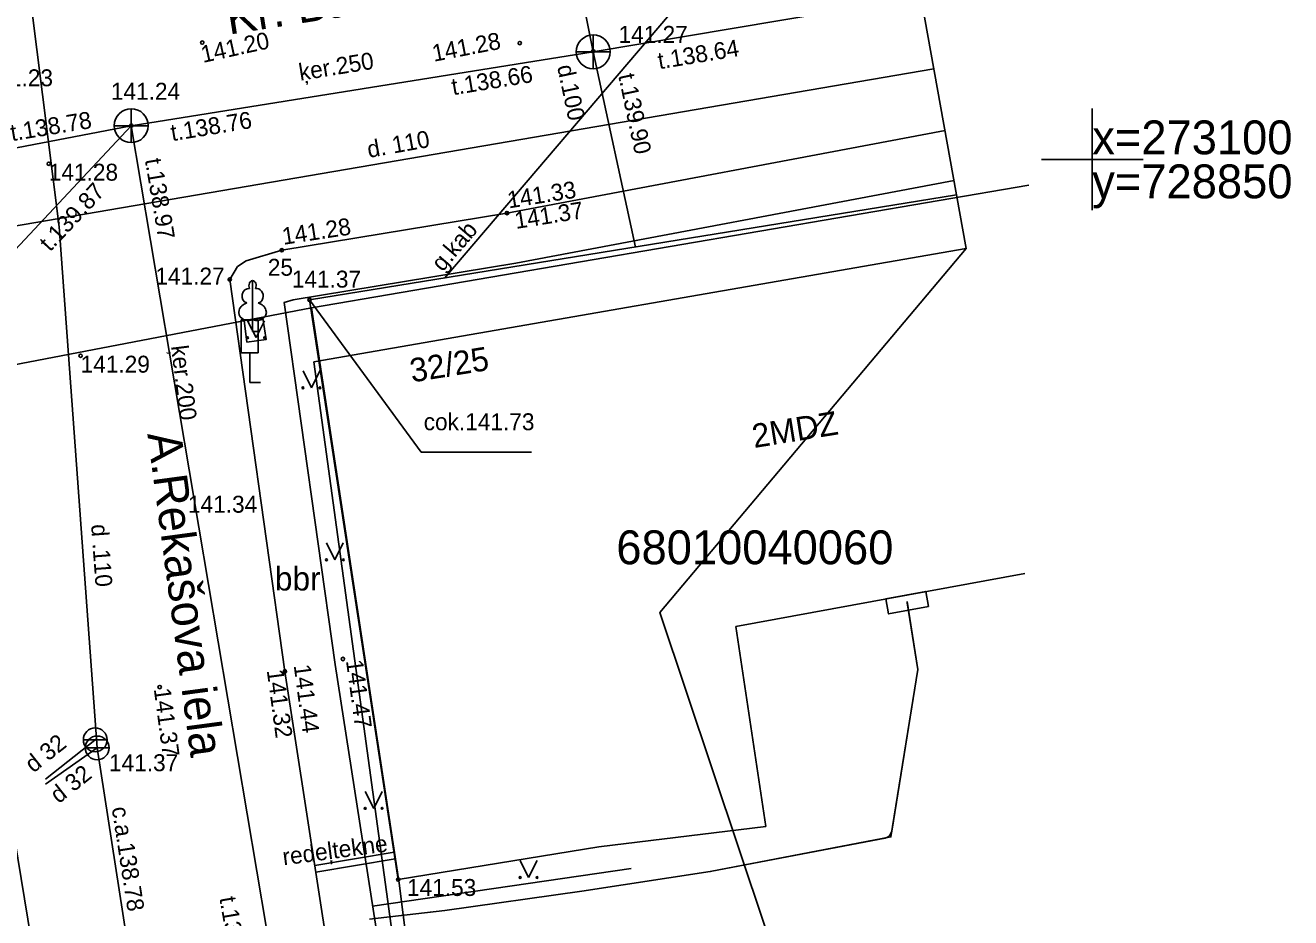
# Model space of a CAD drawing. Extents: x 728710 to 728960, y 272811 to 273475.
# Drawn here: x 728818.5 to 728855.86, y 273077.6 to 273103.96 of the extents above; entities that cross this region are included whole.
import ezdxf

# ---------------------------------------------------------------- set-up
doc = ezdxf.new("R2010")
doc.units = 0
for name, color, linetype in [('GEOD_KORD_####_TKST_#', 7, 'Continuous'), ('Level 10', 7, 'Continuous'), ('Level 15', 7, 'Continuous'), ('Level 17', 7, 'Continuous'), ('Level 23', 7, 'Continuous'), ('Level 29', 7, 'Continuous'), ('Level 3', 7, 'Continuous'), ('Level 36', 7, 'Continuous'), ('Level 39', 7, 'Continuous'), ('Level 4', 7, 'Continuous'), ('Level 48', 7, 'Continuous'), ('Level 49', 7, 'Continuous'), ('Level 50', 7, 'Continuous'), ('Level 54', 7, 'Continuous'), ('Level 55', 7, 'Continuous'), ('Level 57', 7, 'Continuous'), ('Level 58', 7, 'Continuous'), ('Level 59', 7, 'Continuous'), ('Level 60', 7, 'Continuous'), ('Level 62', 7, 'Continuous'), ('Level 9', 7, 'Continuous'), ('PNTNO', 7, 'Continuous'), ('RAMI_UZMR_####_####_#', 7, 'Continuous'), ('RELJ_NOGA_####_####_#', 7, 'Continuous'), ('ROBZ_ELEM_####_####_#', 7, 'Continuous'), ('ROBZ_KADS_####_TKST_#', 7, 'Continuous'), ('ROBZ_UZMR_####_####_#', 7, 'Continuous'), ('SAKT_VADV_PKAB_TKST_#', 7, 'Continuous'), ('TERT_ELEM_####_####_#', 7, 'Continuous'), ('TERT_KONT_####_####_#', 7, 'Continuous')]:
    doc.layers.add(name, color=color, linetype=linetype)

msp = doc.modelspace()

# ---------------------------------------------------------------- linework, layer by layer
at = {"layer": 'Level 10'}
for p, q in [((728850, 273101.5), (728850, 273100)), ((728848.5, 273100), (728850, 273100)), ((728850, 273100), (728850, 273098.5)), ((728850, 273100), (728851.5, 273100))]:
    msp.add_line(p, q, dxfattribs=at)
at = {"layer": 'Level 15'}
msp.add_lwpolyline([(728843.903, 273087.018), (728845.083, 273087.236), (728845.165, 273086.793), (728843.985, 273086.575)], close=True, dxfattribs=at)
at = {"layer": 'Level 17'}
for p, q in [((728845.326, 273102.67), (728810.333, 273096.686)), ((728819.089, 273081.692), (728820.6, 273082.885)), ((728819.097, 273081.543), (728820.62, 273082.615))]:
    msp.add_line(p, q, dxfattribs=at)
for points in [[(728814.387, 273138.519), (728819.492, 273098.009)], [(728819.492, 273098.009), (728820.62, 273082.615)], [(728820.62, 273082.615), (728824.557, 273057.19)]]:
    msp.add_lwpolyline(points, dxfattribs=at)
at = {"layer": 'Level 23'}
for points in [[(728821.624, 273100.995), (728835.266, 273103.178), (728833.756, 273110.699)], [(728835.266, 273103.178), (728844.94, 273104.815)], [(728835.266, 273103.178), (728836.517, 273097.411)], [(728805.243, 273097.85), (728821.624, 273100.995), (728813.478, 273092.29)], [(728821.624, 273100.995), (728826.189, 273073.896), (728840.452, 273076.388)]]:
    msp.add_lwpolyline(points, dxfattribs=at)
at = {"layer": 'Level 29'}
for p, q in [((728835.266, 273102.678), (728835.266, 273103.678)), ((728834.766, 273103.178), (728835.766, 273103.178)), ((728821.624, 273100.495), (728821.624, 273101.495)), ((728821.124, 273100.995), (728822.124, 273100.995))]:
    msp.add_line(p, q, dxfattribs=at)
for centre in [(728835.266, 273103.178), (728821.624, 273100.995)]:
    msp.add_circle(centre, 0.5, dxfattribs=at)
at = {"layer": 'Level 3'}
for p, q in [((728845.995, 273098.953), (728826.892, 273095.851)), ((728826.892, 273095.851), (728829.508, 273078.726)), ((728848.008, 273087.77), (728839.473, 273086.203)), ((728839.473, 273086.203), (728840.359, 273080.29)), ((728840.359, 273080.29), (728835.436, 273079.689)), ((728829.508, 273078.726), (728835.436, 273079.689))]:
    msp.add_line(p, q, dxfattribs=at)
at = {"layer": 'Level 36'}
msp.add_lwpolyline([(728829.43, 273077.644), (728830.885, 273077.81), (728834.933, 273078.385), (728838.722, 273078.96), (728844.053, 273079.984), (728844.848, 273084.934), (728844.534, 273086.905)], dxfattribs=at)
at = {"layer": 'Level 39'}
for p, q in [((728820.211, 273082.855), (728820.913, 273082.855)), ((728820.561, 273082.855), (728820.561, 273082.856)), ((728820.269, 273082.615), (728820.971, 273082.615)), ((728820.619, 273082.615), (728820.619, 273082.616))]:
    msp.add_line(p, q, dxfattribs=at)
for centre in [(728820.562, 273082.855), (728820.62, 273082.615)]:
    msp.add_circle(centre, 0.351, dxfattribs=at)
at = {"layer": 'Level 4'}
for points in [[(728845.654, 273100.85), (728832.719, 273098.413), (728826.071, 273097.316), (728825.017, 273097.001), (728824.765, 273096.832), (728824.532, 273096.455), (728824.532, 273096.455), (728826.161, 273084.877), (728827.437, 273076.575), (728829.749, 273059.3), (728831.728, 273043.761), (728834.021, 273027.538), (728834.782, 273021.709), (728836.279, 273011.943), (728839.357, 272993.501), (728839.499, 272992.383), (728841.21, 272978.381), (728843.301, 272966.86), (728843.797, 272965.94)], [(728845.919, 273099.374), (728832.98, 273096.936), (728826.409, 273095.852), (728826.143, 273095.772), (728827.647, 273085.083), (728828.941, 273076.709), (728831.314, 273059.418), (728833.202, 273044.226), (728835.526, 273027.512), (728836.266, 273021.924), (728837.76, 273012.18), (728840.331, 272994.327), (728840.331, 272994.327), (728840.331, 272994.327), (728842.687, 272979.229), (728844.615, 272968.066)], [(728791.727, 273091.506), (728811.654, 273095.023), (728814.654, 273095.178), (728815.22, 273095.032), (728815.785, 273094.657), (728816.384, 273093.154), (728816.384, 273093.154), (728817.477, 273084.163), (728819.263, 273073.354), (728821.261, 273057.957), (728825.757, 273025.679), (728827.763, 273011.141), (728832.943, 272977.993), (728834.913, 272963.328)], [(728824.957, 273095.241), (728825.042, 273094.601), (728825.605, 273094.676), (728825.508, 273095.31), (728824.957, 273095.241)], [(728828.751, 273077.94), (728836.384, 273079.051)]]:
    msp.add_lwpolyline(points, dxfattribs=at)
at = {"layer": 'Level 48'}
for centre in [(728823.723, 273103.448), (728833.097, 273103.434), (728835.266, 273103.195), (728821.624, 273100.995), (728819.19, 273099.871), (728832.719, 273098.413), (728826.071, 273097.316), (728824.532, 273096.455), (728826.892, 273095.851), (728820.13, 273094.2), (728827.875, 273085.242), (728826.161, 273084.877), (728822.464, 273084.411), (728829.508, 273078.726)]:
    msp.add_circle(centre, 0.05, dxfattribs=at)
at = {"layer": 'Level 49'}
for p, q in [((728825.372, 273095.255), (728824.872, 273095.255)), ((728824.872, 273094.286), (728824.872, 273095.255)), ((728825.372, 273094.286), (728825.372, 273095.255)), ((728825.372, 273094.286), (728824.872, 273094.286)), ((728825.126, 273094.286), (728825.126, 273093.408)), ((728825.126, 273093.408), (728825.441, 273093.408))]:
    msp.add_line(p, q, dxfattribs=at)
at = {"layer": 'Level 9'}
for p, q in [((728829.384, 273079.536), (728827.042, 273079.144)), ((728829.415, 273079.338), (728827.073, 273078.946))]:
    msp.add_line(p, q, dxfattribs=at)
msp.add_lwpolyline([(728826.892, 273095.851), (728830.187, 273091.35), (728833.447, 273091.35)], dxfattribs=at)
at = {"layer": 'RAMI_UZMR_####_####_#'}
for points in [[(728848.126, 273018.981), (728842.745, 273067.512), (728841.027, 273070.984), (728840.357, 273077.286), (728837.229, 273086.616), (728846.28, 273097.37), (728843.445, 273113.117), (728841.542, 273127.507), (728832.527, 273130.942), (728826.701, 273137.145), (728825.388, 273148.763), (728838.211, 273156.68), (728838.026, 273158.297), (728833.202, 273166.507)], [(728830.884, 273096.499), (728844.722, 273112.736)]]:
    msp.add_lwpolyline(points, dxfattribs=at)
at = {"layer": 'ROBZ_ELEM_####_####_#'}
for points in [[(728846.28, 273097.37), (728827.017, 273094.024)], [(728827.017, 273094.024), (728832.315, 273055.38), (728845.254, 272968.134)]]:
    msp.add_lwpolyline(points, dxfattribs=at)
at = {"layer": 'ROBZ_UZMR_####_####_#'}
for p, q in [((728826.945, 273095.617), (728848.13, 273099.241)), ((728812.375, 273092.814), (728826.945, 273095.617)), ((728826.945, 273095.617), (728829.532, 273078.616)), ((728829.532, 273078.616), (728830.131, 273073.976))]:
    msp.add_line(p, q, dxfattribs=at)
at = {"layer": 'TERT_ELEM_####_####_#'}
for points in [[(728844.539, 273086.936), (728844.848, 273084.934), (728844.081, 273080.157)], [(728843.881, 273079.951), (728838.722, 273078.96), (728834.933, 273078.385), (728830.885, 273077.81), (728828.661, 273077.556)]]:
    msp.add_lwpolyline(points, dxfattribs=at)
msp.add_arc((728843.834, 273080.196), 0.25, 280.8732, 350.8759, dxfattribs=at)
at = {"layer": 'TERT_KONT_####_####_#'}
for p, q in [((728825.062, 273095.234), (728825.312, 273094.734)), ((728825.207, 273095.264), (728825.207, 273094.917)), ((728825.312, 273094.734), (728825.562, 273095.234)), ((728825.207, 273094.917), (728825.407, 273094.917)), ((728826.697, 273093.753), (728826.947, 273093.253)), ((728826.947, 273093.253), (728827.197, 273093.753)), ((728827.387, 273088.671), (728827.637, 273088.171)), ((728827.637, 273088.171), (728827.887, 273088.671)), ((728828.533, 273081.33), (728828.783, 273080.83)), ((728828.783, 273080.83), (728829.033, 273081.33)), ((728833.106, 273079.287), (728833.356, 273078.787)), ((728833.356, 273078.787), (728833.606, 273079.287))]:
    msp.add_line(p, q, dxfattribs=at)
for points in [[(728825.207, 273096.417), (728825.207, 273095.264)], [(728825.297, 273096.185), (728825.296, 273096.186)]]:
    msp.add_lwpolyline(points, dxfattribs=at)
for centre, radius in [((728825.062, 273094.733), 0.028), ((728825.562, 273094.733), 0.0263), ((728826.696, 273093.252), 0.028), ((728827.196, 273093.252), 0.0263), ((728827.387, 273088.171), 0.028), ((728827.887, 273088.171), 0.0263), ((728828.532, 273080.83), 0.028), ((728829.032, 273080.83), 0.0263), ((728833.105, 273078.787), 0.028), ((728833.605, 273078.787), 0.0263)]:
    msp.add_circle(centre, radius, dxfattribs=at)
for centre, major_axis, ratio, start_param, end_param in [((728825.079, 273095.972), (-0.039, -0.212), 0.861323, 3.141593, 6.283185), ((728825.207, 273096.267), (0, -0.15), 0.707107, 3.14537, 5.287485), ((728825.207, 273096.267), (0, -0.15), 0.707107, 0.995701, 3.137816), ((728825.335, 273095.972), (0.039, -0.212), 0.861323, 0, 3.141593), ((728825.117, 273095.51), (0.307, 0.095), 0.814445, 1.570796, 4.752015), ((728825.297, 273095.51), (-0.307, 0.095), 0.814445, 1.531171, 4.712389)]:
    msp.add_ellipse(centre, major_axis=major_axis, ratio=ratio, start_param=start_param, end_param=end_param, dxfattribs=at)

# ---------------------------------------------------------------- texts
at = {"layer": 'GEOD_KORD_####_TKST_#'}
for s, p in [('x=273100', (728850, 273100.15)), ('y=728850', (728850, 273098.85))]:
    msp.add_text(s, height=1, dxfattribs=at).set_placement(p)
at = {"layer": 'Level 29'}
for s, p in [('141.27', (728836.013, 273103.442)), ('141.24', (728821.023, 273101.761))]:
    msp.add_text(s, height=0.5, dxfattribs=at).set_placement(p)
at = {"layer": 'Level 50'}
msp.add_text('cok.141.73', height=0.5, dxfattribs=at).set_placement((728830.26, 273091.999))
at = {"layer": 'Level 54'}
for s, rotation, p in [('Kr. Barona iela', 8.9676, (728824.513, 273103.683)), ('A.Rekašova iela', 277.641, (728822.099, 273091.891))]:
    msp.add_text(s, height=1, rotation=rotation, dxfattribs=at).set_placement(p)
at = {"layer": 'Level 55'}
for s, rotation, p in [('d. 110', 10.171, (728828.639, 273100.041)), ('d .110', 274.1909, (728820.438, 273089.209)), ('d 32', 38.5497, (728818.736, 273081.86)), ('d 32', 38.4214, (728819.481, 273080.952)), ('c.a.138.78', 278.8022, (728821.046, 273080.844))]:
    msp.add_text(s, height=0.5, rotation=rotation, dxfattribs=at).set_placement(p)
at = {"layer": 'Level 57'}
for s, rotation, p in [('141.20', 12.3724, (728823.743, 273102.848)), ('141.28', 10.9426, (728830.56, 273102.882)), ('141.33', 9.0652, (728832.771, 273098.55)), ('141.37', 9.0266, (728832.985, 273097.944)), ('141.28', 8.6712, (728826.118, 273097.475)), ('141.44', 277.4911, (728826.421, 273085.054)), ('141.47', 277.7155, (728827.964, 273085.19)), ('141.32', 277.6342, (728825.625, 273084.905)), ('141.37', 277.5622, (728822.29, 273084.354))]:
    msp.add_text(s, height=0.5, rotation=rotation, dxfattribs=at).set_placement(p)
for s, p in [('141.23', (728817.27, 273102.159)), ('141.28', (728819.19, 273099.371)), ('141.27', (728822.337, 273096.302)), ('141.37', (728826.366, 273096.212)), ('141.29', (728820.13, 273093.7)), (' 141.34', (728823.114, 273089.563)), (' 141.53', (728829.581, 273078.242))]:
    msp.add_text(s, height=0.5, dxfattribs=at).set_placement(p)
at = {"layer": 'Level 58'}
msp.add_text('bbr', height=0.7, dxfattribs=at).set_placement((728825.865, 273087.265))
at = {"layer": 'Level 59'}
msp.add_text('2MDZ', height=0.7, rotation=9.224, dxfattribs=at).set_placement((728840.017, 273091.472))
at = {"layer": 'Level 60'}
for s, rotation, p in [('t.138.64', 9.426, (728837.216, 273102.66)), ('ķer.250', 9.272, (728826.615, 273102.321)), ('t.138.66', 9.426, (728831.127, 273101.892)), ('d.100', 281.932, (728834.197, 273102.744)), ('t.139.90', 281.932, (728836.002, 273102.481)), ('t.138.78', 9.383, (728818.101, 273100.536)), ('t.138.76', 9.383, (728822.833, 273100.536)), ('t.138.97', 279.562, (728822.025, 273099.989)), ('t.139.87', 46.899, (728819.226, 273097.251)), ('ķer.200', 277.044, (728822.797, 273094.48)), ('t.139.30', 279.562, (728824.227, 273078.183))]:
    msp.add_text(s, height=0.5, rotation=rotation, dxfattribs=at).set_placement(p)
at = {"layer": 'Level 62'}
msp.add_text('32/25', height=0.7, rotation=9.224, dxfattribs=at).set_placement((728829.913, 273093.408))
at = {"layer": 'Level 9'}
msp.add_text('redeļtekne', height=0.5, rotation=7.5675, dxfattribs=at).set_placement((728826.124, 273079.145))
at = {"layer": 'PNTNO'}
msp.add_text(' 141.37', height=0.5, dxfattribs=at).set_placement((728820.782, 273081.928))
at = {"layer": 'RELJ_NOGA_####_####_#'}
msp.add_text('25', height=0.5, dxfattribs=at).set_placement((728825.657, 273096.562))
at = {"layer": 'ROBZ_KADS_####_TKST_#'}
msp.add_text('68010040060', height=1, dxfattribs=at).set_placement((728835.948, 273088.04))
at = {"layer": 'SAKT_VADV_PKAB_TKST_#'}
msp.add_text('g.kab', height=0.5, rotation=49.5607, dxfattribs=at).set_placement((728830.82, 273096.656))

doc.saveas('drawing.dxf')
